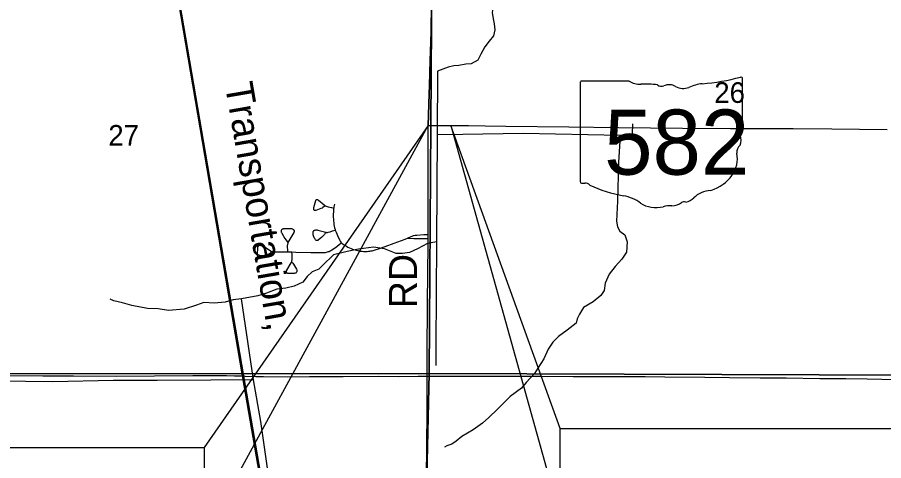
# Model space of a CAD drawing. Extents: x 0 to 34, y 0 to 22.
# Drawn here: x 4.664 to 6.42, y 16.867 to 17.765 of the extents above; entities that cross this region are included whole.
import ezdxf

# ---------------------------------------------------------------- set-up
doc = ezdxf.new("R2010")
doc.units = 0
for name, color, linetype in [('GM_X_County_Road', 7, 'Continuous'), ('GM_X_County_Road_Text', 7, 'Continuous'), ('GM_X_Minor_River', 7, 'Continuous'), ('GM_X_Rail_Line', 7, 'Continuous'), ('GM_X_Rail_Line_Text', 7, 'Continuous'), ('GM_X_Section', 7, 'Continuous'), ('GM_X_Section_Text', 7, 'Continuous'), ('GM_X_State_Location', 7, 'Continuous'), ('GM_X_State_Route', 7, 'Continuous'), ('GM_X_State_Shield', 7, 'Continuous'), ('GM_X_Township_Road', 7, 'Continuous'), ('SH_Data', 7, 'Continuous'), ('SH_Text', 7, 'Continuous'), ('TX_P_1', 7, 'Continuous')]:
    doc.layers.add(name, color=color, linetype=linetype)

msp = doc.modelspace()

# ---------------------------------------------------------------- linework, layer by layer
at = {"layer": 'GM_X_County_Road'}
for points in [[(5.4967, 17.5463), (5.4988, 17.61), (5.4994, 17.6274), (5.5009, 17.6779), (5.5019, 17.7158), (5.5025, 17.7373), (5.503, 17.7535), (5.5041, 17.7977)], [(5.4965, 17.3171), (5.4966, 17.3254), (5.4967, 17.3375), (5.4967, 17.3642), (5.4967, 17.4003), (5.4965, 17.4258), (5.4965, 17.4401), (5.4964, 17.4674), (5.4966, 17.5083), (5.4967, 17.5463)], [(5.4947, 17.038), (5.4947, 17.0461), (5.4948, 17.0913), (5.4957, 17.1771), (5.4963, 17.2548), (5.4966, 17.2959), (5.4965, 17.3164), (5.4965, 17.3171)], [(5.4866, 16.5301), (5.4875, 16.5679), (5.4888, 16.6189), (5.4891, 16.6437), (5.4897, 16.6823), (5.4908, 16.7239), (5.492, 16.7867), (5.4931, 16.8433), (5.4937, 16.8855), (5.4939, 16.9067), (5.4945, 16.9576), (5.4946, 17.0204), (5.4947, 17.038)]]:
    msp.add_lwpolyline(points, dxfattribs=at)
at = {"layer": 'GM_X_Minor_River'}
for points in [[(5.6594, 17.8666), (5.6557, 17.853), (5.6485, 17.8384), (5.6437, 17.8267), (5.6411, 17.8135), (5.6355, 17.8011), (5.6287, 17.7873), (5.6265, 17.7752), (5.6288, 17.7622), (5.6309, 17.7523), (5.6317, 17.7401), (5.6291, 17.7277), (5.6205, 17.7169), (5.6119, 17.7057), (5.6036, 17.6907), (5.5972, 17.6787), (5.5842, 17.6714), (5.5728, 17.6702), (5.5587, 17.6679), (5.5488, 17.667), (5.5374, 17.6642), (5.5156, 17.656)], [(5.5156, 17.656), (5.5147, 17.527), (5.5135, 17.3104), (5.5124, 17.0998), (5.5122, 17.0599)], [(5.9114, 17.5497), (5.9101, 17.5285), (5.8858, 17.526), (5.6893, 17.5296), (5.5667, 17.5277), (5.5147, 17.527)], [(5.8858, 17.526), (5.8825, 17.4711), (5.8806, 17.3925), (5.8784, 17.3524), (5.8804, 17.3409), (5.8855, 17.3321), (5.8955, 17.3243), (5.9001, 17.3101), (5.8992, 17.2896), (5.8898, 17.2751), (5.8762, 17.2602), (5.8637, 17.245), (5.856, 17.2265), (5.8534, 17.2118), (5.8471, 17.2017), (5.8316, 17.1888), (5.812, 17.1771), (5.8033, 17.1641), (5.7989, 17.1543), (5.7968, 17.1456), (5.7787, 17.1313), (5.7613, 17.1184), (5.7497, 17.1073), (5.7402, 17.0927), (5.731, 17.0732), (5.7192, 17.0542), (5.7125, 17.0437), (5.6957, 17.0255), (5.686, 17.014), (5.6628, 16.9967), (5.6372, 16.9715), (5.6197, 16.9541), (5.6066, 16.9427), (5.5877, 16.9291), (5.5765, 16.9225), (5.565, 16.9156), (5.5538, 16.9064), (5.5446, 16.9005), (5.5343, 16.897), (5.5296, 16.8944)], [(5.5135, 17.3104), (5.4956, 17.307), (5.4753, 17.2965), (5.4588, 17.2885), (5.4447, 17.2866), (5.4318, 17.2865), (5.4082, 17.2962), (5.386, 17.2998), (5.3552, 17.2952), (5.3327, 17.2908), (5.3045, 17.2843), (5.2824, 17.2621), (5.2747, 17.255), (5.2613, 17.2493), (5.2512, 17.2401), (5.2426, 17.2289), (5.2253, 17.2206), (5.2078, 17.2168), (5.1896, 17.2142), (5.1689, 17.2064), (5.151, 17.2011), (5.1183, 17.1951), (5.1016, 17.1928), (5.0852, 17.1883), (5.0628, 17.1862), (5.042, 17.1874), (5.0267, 17.1817), (5.0022, 17.1736), (4.9704, 17.1713), (4.9493, 17.1749), (4.9277, 17.1754), (4.8956, 17.1811), (4.8768, 17.1865), (4.8591, 17.1911), (4.852, 17.1943)], [(5.3189, 15.9417), (5.2959, 16.0838), (5.2634, 16.2838), (5.2253, 16.5197), (5.1957, 16.7006), (5.1705, 16.8565), (5.1572, 16.9463), (5.1426, 17.0309), (5.1183, 17.1951)], [(5.1426, 17.0309), (5.0559, 17.03), (4.9471, 17.0292), (4.8582, 17.0291), (4.7358, 17.0264), (4.6241, 17.0283), (4.4946, 17.028), (4.4135, 17.0269), (4.4037, 17.0295), (4.3938, 17.0274), (4.3811, 17.0179), (4.3614, 17.0039), (4.3403, 16.9927), (4.3158, 16.9792), (4.2631, 16.9482), (4.2374, 16.9344), (4.2229, 16.9299), (4.2092, 16.9279), (4.1587, 16.9219)]]:
    msp.add_lwpolyline(points, dxfattribs=at)
at = {"layer": 'GM_X_Rail_Line'}
for points in [[(5.5292, 14.4768), (5.5206, 14.546), (5.4959, 14.7503), (5.4725, 14.9371), (5.462, 15.0205), (5.4461, 15.156), (5.4028, 15.3982), (5.2961, 16.0228), (5.1204, 17.0387), (4.9909, 17.7947), (4.7368, 19.2661), (4.6073, 20.0278), (4.4575, 20.9)], [(5.5755, 14.1), (5.542, 14.3915), (5.5241, 14.5438), (5.4984, 14.7506), (5.475, 14.9374), (5.4645, 15.0208), (5.4485, 15.1564), (5.4052, 15.3987), (5.2986, 16.0233), (5.1228, 17.0391), (4.9933, 17.7951), (4.7392, 19.2665), (4.6097, 20.0282), (4.4576, 20.9)]]:
    msp.add_lwpolyline(points, dxfattribs=at)
at = {"layer": 'GM_X_Section'}
for points in [[(5.5052, 18.0545), (5.4985, 17.0434), (4.4954, 17.0428), (4.5012, 18.0497)], [(6.5049, 18.0487), (6.488, 17.04), (5.4985, 17.0434), (5.5052, 18.0545)]]:
    msp.add_lwpolyline(points, close=True, dxfattribs=at)
for points in [[(4.4929, 16.8935), (4.4954, 17.0428), (5.4985, 17.0434), (5.476, 16.0344), (5.457, 16.0346), (4.4786, 16.0375), (4.4803, 16.1435)], [(6.4705, 16.1819), (6.4673, 16.0279), (6.437, 16.0283), (5.476, 16.0344), (5.4985, 17.0434), (6.488, 17.04), (6.4858, 16.9319)]]:
    msp.add_lwpolyline(points, dxfattribs=at)
at = {"layer": 'GM_X_State_Route'}
for points in [[(5.5041, 17.7977), (5.503, 17.7535), (5.5025, 17.7373), (5.5019, 17.7158), (5.5009, 17.6779), (5.4994, 17.6274), (5.4988, 17.61), (5.4967, 17.5463)], [(5.4967, 17.5463), (5.5316, 17.5463), (5.5783, 17.5458), (5.6125, 17.5457), (5.6541, 17.5451), (5.7821, 17.5437), (5.8829, 17.5422), (6.0128, 17.5407), (6.1097, 17.5402), (6.1582, 17.5401), (6.2372, 17.54), (6.3156, 17.5391), (6.4274, 17.538)]]:
    msp.add_lwpolyline(points, dxfattribs=at)
at = {"layer": 'GM_X_State_Shield'}
for p, q in [((6.1343, 17.5363), (6.1343, 17.641)), ((5.8047, 17.6326), (5.8047, 17.4324)), ((5.9045, 17.636), (5.808, 17.636)), ((6.1343, 17.5363), (6.1343, 17.5363))]:
    msp.add_line(p, q, dxfattribs=at)
for centre, major_axis, start_param, end_param in [((6.0169, 17.9088), (0.3495, 0), 4.814394, 5.042369), ((6.1306, 17.6414), (0.00367, 0), 6.141152, 7.989035), ((5.8085, 17.633), (0.00382, 0), 1.712693, 3.28349), ((5.9275, 17.6592), (0.037, 0), 4.042523, 4.731795), ((5.9397, 17.5236), (0.133, 0), 1.404758, 1.657858), ((5.9699, 17.634), (0.0107, 0), 3.836095, 5.185415), ((5.9856, 17.6109), (0.0222, 0), 0.950623, 2.079405), ((6.0143, 17.6426), (0.0267, 0), 4.081561, 5.145723), ((6.0615, 17.5749), (0.0703, 0), 1.699011, 2.107814), ((6.1304, 17.5359), (0.00393, 0), 5.05454, 6.418171), ((6.1334, 17.5286), (0.00568, 0), 1.883978, 3.671073), ((6.0973, 17.5154), (0.0341, 0), 5.934695, 6.695948), ((6.1474, 17.4925), (0.0248, 0), 2.387724, 3.262537), ((6.0365, 17.4791), (0.0874, 0), 5.101752, 6.440018), ((5.8085, 17.432), (0.00385, 0), 3.00124, 4.508301), ((5.8091, 17.4525), (0.0294, 0), 4.665946, 4.897461), ((5.8151, 17.4209), (0.0106, 0), 0.519207, 1.627899), ((5.9489, 17.6007), (0.2524, 0), 4.195997, 4.488961), ((6.0733, 17.3762), (0.0479, 0), 1.647645, 2.488434), ((5.8737, 17.3425), (0.079, 0), 0.823519, 1.323587), ((6.0127, 17.413), (0.0282, 0), 4.937069, 5.64225), ((5.9591, 17.4199), (0.0501, 0), 4.026481, 4.996735), ((5.9881, 17.3507), (0.0412, 0), 1.495662, 1.94098), ((5.9917, 17.4049), (0.0267, 0), 4.691044, 5.507374), ((6.0159, 17.3855), (0.00752, 0), 1.147584, 2.315152)]:
    msp.add_ellipse(centre, major_axis=major_axis, ratio=0.8, start_param=start_param, end_param=end_param, dxfattribs=at)
at = {"layer": 'GM_X_Township_Road'}
msp.add_line((5.212, 17.2898), (5.2205, 17.2898), dxfattribs=at)
for points in [[(5.288, 17.3831), (5.2833, 17.3798), (5.2817, 17.3789), (5.2791, 17.3778), (5.2689, 17.374), (5.2676, 17.3737), (5.2669, 17.3737), (5.2662, 17.3738), (5.2654, 17.3742), (5.2649, 17.3749), (5.2646, 17.3758), (5.2646, 17.3768), (5.2651, 17.3798), (5.269, 17.3943), (5.2692, 17.395), (5.2699, 17.3958), (5.2704, 17.3962), (5.2716, 17.3963), (5.2723, 17.3962), (5.2733, 17.3956), (5.2741, 17.3951), (5.2856, 17.3854), (5.287, 17.3843), (5.2887, 17.3832), (5.2901, 17.3825), (5.2916, 17.382), (5.294, 17.3814), (5.3006, 17.3801), (5.3053, 17.3789)], [(5.3053, 17.3789), (5.3051, 17.3771), (5.3045, 17.3703), (5.3043, 17.3673), (5.3043, 17.3644), (5.3044, 17.36), (5.3046, 17.3569), (5.3049, 17.3528), (5.3053, 17.3491), (5.3057, 17.3453), (5.3063, 17.3419), (5.3068, 17.3388), (5.3079, 17.3355), (5.3084, 17.3343)], [(5.3069, 17.3864), (5.3062, 17.384), (5.3057, 17.3814), (5.3053, 17.3789)], [(5.212, 17.2898), (5.2118, 17.3037), (5.2119, 17.3052), (5.2121, 17.3062), (5.2126, 17.3076), (5.2131, 17.3089), (5.2249, 17.3296), (5.2252, 17.3305), (5.2254, 17.3311), (5.2255, 17.3321), (5.2255, 17.3328), (5.2253, 17.3335), (5.2249, 17.334), (5.2244, 17.3345), (5.2239, 17.335), (5.2232, 17.3354), (5.2223, 17.3358), (5.2213, 17.3362), (5.2202, 17.3365), (5.219, 17.3367), (5.2057, 17.3366), (5.2028, 17.3364), (5.202, 17.3363), (5.201, 17.336), (5.2002, 17.3356), (5.1993, 17.3347), (5.1987, 17.3335), (5.1985, 17.3327), (5.1984, 17.332), (5.1985, 17.3312), (5.1987, 17.3303), (5.1992, 17.329), (5.1997, 17.3279), (5.2063, 17.3168), (5.2125, 17.3086)], [(5.2888, 17.3293), (5.2863, 17.3254), (5.2854, 17.3241), (5.2845, 17.3229), (5.281, 17.3197), (5.274, 17.3138), (5.2731, 17.3132), (5.2724, 17.3129), (5.2717, 17.3128), (5.271, 17.3128), (5.2703, 17.313), (5.2696, 17.3133), (5.269, 17.3138), (5.2683, 17.3146), (5.2675, 17.3158), (5.2667, 17.317), (5.2658, 17.3188), (5.265, 17.3207), (5.2643, 17.3225), (5.2638, 17.3245), (5.2636, 17.3261), (5.2635, 17.3274), (5.2633, 17.3287), (5.2634, 17.3296), (5.2636, 17.3306), (5.2638, 17.3315), (5.2642, 17.3321), (5.2646, 17.3327), (5.2652, 17.3332), (5.2662, 17.3337), (5.2673, 17.3341), (5.2688, 17.3344), (5.2705, 17.3346), (5.2718, 17.3345), (5.2732, 17.3343), (5.289, 17.3297), (5.2902, 17.3295), (5.2914, 17.3294), (5.2928, 17.3295), (5.294, 17.3297), (5.2978, 17.3309), (5.3028, 17.3325), (5.3084, 17.3343)], [(5.3084, 17.3343), (5.31, 17.3301), (5.3129, 17.3231), (5.3169, 17.3142), (5.3177, 17.3129), (5.3186, 17.3114), (5.3196, 17.31), (5.3208, 17.3086)], [(5.4549, 17.3177), (5.462, 17.3211), (5.4642, 17.322), (5.4671, 17.3229), (5.4704, 17.3236), (5.4738, 17.3242), (5.4879, 17.3252), (5.4966, 17.3254)], [(5.2205, 17.2898), (5.2287, 17.2896), (5.2585, 17.289), (5.2858, 17.2889), (5.2883, 17.2891), (5.2907, 17.2893), (5.2925, 17.2898), (5.2945, 17.2905), (5.2959, 17.2911), (5.2977, 17.2919), (5.2994, 17.2928), (5.3014, 17.2939), (5.3047, 17.296), (5.3113, 17.3009), (5.3171, 17.3056), (5.3208, 17.3086)], [(5.3208, 17.3086), (5.3221, 17.3073), (5.3242, 17.3056), (5.3262, 17.3042), (5.3285, 17.3027), (5.3308, 17.3014), (5.3339, 17.2998), (5.337, 17.2983), (5.3404, 17.2969), (5.3432, 17.2958), (5.346, 17.2949), (5.3486, 17.2942), (5.3516, 17.2933), (5.3543, 17.2926), (5.3562, 17.2922), (5.3582, 17.2918), (5.3606, 17.2915), (5.3631, 17.2913), (5.3657, 17.2911), (5.3694, 17.2911), (5.3728, 17.2911), (5.3759, 17.2914), (5.3783, 17.2916), (5.3806, 17.2919), (5.3831, 17.2924), (5.3853, 17.2928), (5.3895, 17.2939), (5.3961, 17.2959), (5.4096, 17.3008), (5.4281, 17.308), (5.4498, 17.3159), (5.4549, 17.3177)], [(5.4549, 17.3177), (5.4678, 17.3169), (5.4913, 17.3171), (5.4965, 17.3171)], [(5.1789, 17.2906), (5.1765, 17.2874), (5.1755, 17.2865), (5.1745, 17.2858), (5.1737, 17.2853), (5.1654, 17.2807), (5.1584, 17.2775), (5.1574, 17.2772), (5.1563, 17.2771), (5.1553, 17.2771), (5.1543, 17.2773), (5.1536, 17.2776), (5.1528, 17.278), (5.1521, 17.2785), (5.1516, 17.2791), (5.1512, 17.2797), (5.151, 17.2804), (5.1507, 17.2817), (5.1506, 17.2854), (5.1511, 17.2976), (5.1513, 17.2994), (5.1516, 17.3003), (5.1519, 17.3011), (5.1526, 17.302), (5.1532, 17.3026), (5.154, 17.3031), (5.1548, 17.3034), (5.1557, 17.3036), (5.1568, 17.3037), (5.158, 17.3036), (5.1591, 17.3033), (5.1601, 17.3029), (5.167, 17.2989), (5.1783, 17.2915), (5.1793, 17.291), (5.1803, 17.2906), (5.1813, 17.2904), (5.1827, 17.2902), (5.212, 17.2898)], [(5.2201, 17.2691), (5.2224, 17.267), (5.2236, 17.2654), (5.226, 17.2619), (5.228, 17.2581), (5.2296, 17.2549), (5.2301, 17.2537), (5.2304, 17.2526), (5.2306, 17.2515), (5.2305, 17.2507), (5.2304, 17.2499), (5.2301, 17.2493), (5.2298, 17.2486), (5.2289, 17.2476), (5.2283, 17.2472), (5.2275, 17.2469), (5.2266, 17.2466), (5.2252, 17.2464), (5.2137, 17.2462), (5.2127, 17.2463), (5.212, 17.2465), (5.2111, 17.247), (5.2104, 17.2476), (5.21, 17.2481), (5.2097, 17.2488), (5.2095, 17.2497), (5.2095, 17.2506), (5.2097, 17.2516), (5.2099, 17.2525), (5.2103, 17.2533), (5.2192, 17.2679), (5.2198, 17.2695), (5.2203, 17.2708), (5.2206, 17.2724), (5.2208, 17.2739), (5.2207, 17.2837), (5.2205, 17.2898)], [(4.4875, 17.0392), (4.513, 17.0392), (4.5908, 17.0393), (4.7151, 17.039), (4.7773, 17.0386), (4.8643, 17.0384), (5.0197, 17.0392), (5.0663, 17.0396), (5.0881, 17.0395), (5.1037, 17.0391), (5.1192, 17.0385), (5.1254, 17.0383), (5.1471, 17.0377), (5.1626, 17.0374), (5.2123, 17.0371), (5.2558, 17.0372), (5.3242, 17.0377), (5.3957, 17.0379), (5.4361, 17.0378), (5.4765, 17.0381), (5.4947, 17.038)], [(5.4947, 17.038), (5.5107, 17.038), (5.548, 17.038), (5.5822, 17.038), (5.6755, 17.0381), (5.7252, 17.0381), (5.7905, 17.0376), (5.8526, 17.0374), (5.9024, 17.0377), (5.9366, 17.0373), (5.977, 17.0369), (6.0578, 17.036), (6.1075, 17.0354), (6.1697, 17.0349), (6.2225, 17.0345), (6.2909, 17.0337), (6.3437, 17.0332), (6.3872, 17.0325), (6.4463, 17.0314), (6.4711, 17.0309), (6.4866, 17.031), (6.4919, 17.0313)]]:
    msp.add_lwpolyline(points, dxfattribs=at)
at = {"layer": 'SH_Data'}
msp.add_line((5.4967, 17.5463), (5.5424, 17.5463), dxfattribs=at)
at = {"layer": 'SH_Text'}
for points in [[(5.7647, 16.9319), (7.7647, 16.9319), (7.7647, 16.1819), (5.7647, 16.1819)], [(3.0426, 16.8935), (5.0426, 16.8935), (5.0426, 16.1435), (3.0426, 16.1435)]]:
    msp.add_lwpolyline(points, close=True, dxfattribs=at)
at = {"layer": 'TX_P_1'}
for points in [[(5.0426, 16.7134), (5.4967, 17.5463), (5.0426, 16.8935)], [(5.7647, 16.9319), (5.5424, 17.5463), (5.7647, 16.7518)]]:
    msp.add_lwpolyline(points, close=True, dxfattribs=at)

# ---------------------------------------------------------------- texts
at = {"layer": 'GM_X_County_Road_Text'}
msp.add_text('RD', height=0.05682, rotation=90, dxfattribs=at).set_placement((5.4741, 17.176))
at = {"layer": 'GM_X_Rail_Line_Text'}
msp.add_text('Transportation,', height=0.056629, rotation=279.7939, dxfattribs=at).set_placement((5.0843, 17.6289))
at = {"layer": 'GM_X_Section_Text'}
for s, p in [('26', (6.0769, 17.5919)), ('27', (4.8481, 17.5052))]:
    msp.add_text(s, height=0.04186, rotation=0, dxfattribs=at).set_placement(p)
at = {"layer": 'GM_X_State_Location'}
for s in ['s', 'r']:
    msp.add_text(s, height=0.000189, dxfattribs=at).set_placement((5.9658, 17.5192))
msp.add_text('582', height=0.000189, rotation=0, dxfattribs=at).set_placement((5.8989, 17.5054))
at = {"layer": 'GM_X_State_Shield'}
msp.add_text('582', height=0.13184, dxfattribs=at).set_placement((5.8537, 17.4465))

doc.saveas('drawing.dxf')
